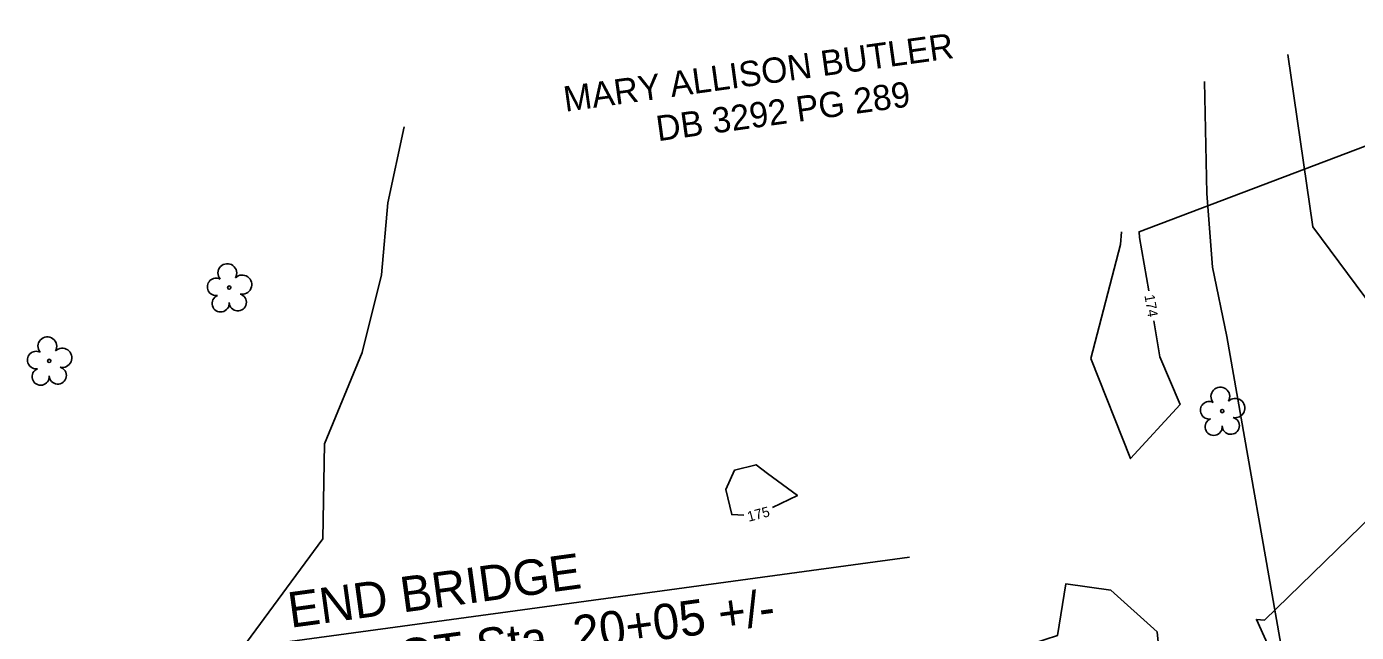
# Model space of a CAD drawing. Extents: x 2086416 to 2115205, y 575507 to 632762.
# Drawn here: x 2112093.5 to 2112356.1, y 581852.1 to 581971.8 of the extents above; entities that cross this region are included whole.
import ezdxf

# ---------------------------------------------------------------- set-up
doc = ezdxf.new("R2010")
doc.units = 0
for name, color, linetype in [('DTM Contours Major', 7, 'Continuous'), ('DTM Contours Major Text', 7, 'Continuous'), ('DTM Contours Minor', 7, 'Continuous'), ('DTM Contours Minor Text', 7, 'Continuous'), ('Exist Hydro Stream or Body of Water', 7, 'Continuous'), ('Exist Property Deed Book Text', 7, 'Continuous'), ('Exist Property Owner Text', 7, 'Continuous'), ('Exist Vegetation Tree CELL', 7, 'Continuous'), ('Exist Vegetation Woods Line', 7, 'Continuous'), ('Prop Horizontal Alignment Station Label', 7, 'Continuous')]:
    doc.layers.add(name, color=color, linetype=linetype)

# ---------------------------------------------------------------- blocks, each defined once
blk = doc.blocks.new('EXIST VEGETATION TREE')
at = {"layer": 'Exist Vegetation Tree CELL'}
blk.add_line((0, 0), (0, 0), dxfattribs=at)
blk.add_circle((0, 0), 0.00652, dxfattribs=at)
for centre, radius, start, end in [((-0.0077, 0.0575), 0.0371, 330.1651, 219.7134), ((-0.0521, 0.0031), 0.0345, 62.6636, 279.3457), ((0.051, 0.0118), 0.038, 257.1011, 134.1999), ((-0.0341, -0.0624), 0.0338, 111.5671, 6.231), ((0.0335, -0.058), 0.034, 181.2822, 74.56)]:
    blk.add_arc(centre, radius, start, end, dxfattribs=at)

msp = doc.modelspace()

# ---------------------------------------------------------------- linework, layer by layer
at = {"layer": 'DTM Contours Major'}
for points in [[(2112239.77, 581883.48), (2112237.54, 581885.22), (2112233.31, 581884.15), (2112231.58, 581880.32), (2112232.74, 581875.35), (2112235.11, 581875.27)], [(2112240.76, 581876.76), (2112245.72, 581879.1), (2112239.77, 581883.48)], [(2112307.63, 581860.46), (2112298.69, 581861.68), (2112297.08, 581851.5), (2112289.78, 581849.11), (2112291.03, 581843.54), (2112279.58, 581824.63), (2112299.71, 581826.22), (2112319.48, 581829.38), (2112318.75, 581834.28)], [(2112317.96, 581840.23), (2112316.72, 581852.2), (2112307.63, 581860.46)]]:
    msp.add_lwpolyline(points, dxfattribs=at)
at = {"layer": 'DTM Contours Minor'}
for points in [[(2112315.08, 581919.53), (2112313.29, 581930.07), (2112313.19, 581931.24), (2112370.35, 581952.85)], [(2112309.71, 581931.19), (2112309.53, 581928.69), (2112303.62, 581906.17), (2112311.46, 581886.42), (2112321.28, 581897.08), (2112317.29, 581906.53), (2112316.08, 581913.62)], [(2112254.07, 581816.2), (2112270.16, 581818.14), (2112276.22, 581818.7), (2112299.96, 581821.57), (2112307.56, 581822.62), (2112329.58, 581826.32), (2112343.62, 581828.68), (2112345.41, 581828.91), (2112345.86, 581828.8), (2112351.13, 581828.16), (2112351.3, 581828.82), (2112352.42, 581829.9), (2112349.84, 581834.07), (2112347.16, 581839.69), (2112345.41, 581840.74), (2112341.86, 581842.42), (2112341.8, 581842.53), (2112336.33, 581854.64), (2112337.93, 581854.53), (2112361.72, 581877.6), (2112365.19, 581879.81), (2112375.59, 581882.41), (2112386.63, 581894.46), (2112387.61, 581897.62)]]:
    msp.add_lwpolyline(points, dxfattribs=at)
at = {"layer": 'Exist Hydro Stream or Body of Water'}
for points in [[(2112342.28, 581843.38), (2112330.53, 581910.52), (2112327.68, 581924.24), (2112326.53, 581938.77), (2112326.09, 581960.89)], [(2112117.41, 581823.6), (2112152.01, 581870.55), (2112152.35, 581889.35), (2112159.73, 581907.41), (2112163.61, 581922.72), (2112164.82, 581936.95), (2112168.08, 581951.98)]]:
    msp.add_lwpolyline(points, dxfattribs=at)
at = {"layer": 'Exist Vegetation Woods Line'}
msp.add_lwpolyline([(2112393.84, 581971.76), (2112391.03, 581944.12), (2112388.74, 581921.66), (2112364.61, 581909.13), (2112347.49, 581932.18), (2112342.54, 581966.24)], dxfattribs=at)
at = {"layer": 'Prop Horizontal Alignment Station Label'}
msp.add_line((2112135.81, 581848.95), (2112267.87, 581866.97), dxfattribs=at)

# ---------------------------------------------------------------- block references
at = {"layer": 'Exist Vegetation Tree CELL', "xscale": 50, "yscale": 50}
for p in [(2112133.52, 581920.19), (2112097.98, 581905.73), (2112329.61, 581895.81)]:
    msp.add_blockref('EXIST VEGETATION TREE', p, dxfattribs=at)

# ---------------------------------------------------------------- texts
at = {"layer": 'DTM Contours Major Text'}
msp.add_text('175', height=2, rotation=14.7785, dxfattribs=at).set_placement((2112236.1, 581873.93))
at = {"layer": 'DTM Contours Minor Text'}
msp.add_text('174', height=2, rotation=279.6332, dxfattribs=at).set_placement((2112314.22, 581918.65))
at = {"layer": 'Exist Property Deed Book Text'}
msp.add_text('DB 3292 PG 289', height=5, rotation=7.8831, dxfattribs=at).set_placement((2112218.17, 581949.1))
at = {"layer": 'Exist Property Owner Text'}
msp.add_text('MARY ALLISON BUTLER', height=5, rotation=7.883, dxfattribs=at).set_placement((2112199.88, 581954.92))
at = {"layer": 'Prop Horizontal Alignment Station Label'}
for s, p in [('END BRIDGE', (2112145.62, 581852.98)), ('-L- POT Sta. 20+05 +/-  ', (2112147.27, 581840.84))]:
    msp.add_text(s, height=7, rotation=7.771, dxfattribs=at).set_placement(p)

doc.saveas('drawing.dxf')
